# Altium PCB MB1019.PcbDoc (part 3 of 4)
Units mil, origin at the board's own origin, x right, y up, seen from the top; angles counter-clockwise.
Board outline 4655 x 6805 mil, 4 copper layers (TopLayer, VCC, GND, BottomLayer), stack 26.137 mil thick; 557 components, 425 nets, 1918 pads, 817 vias.
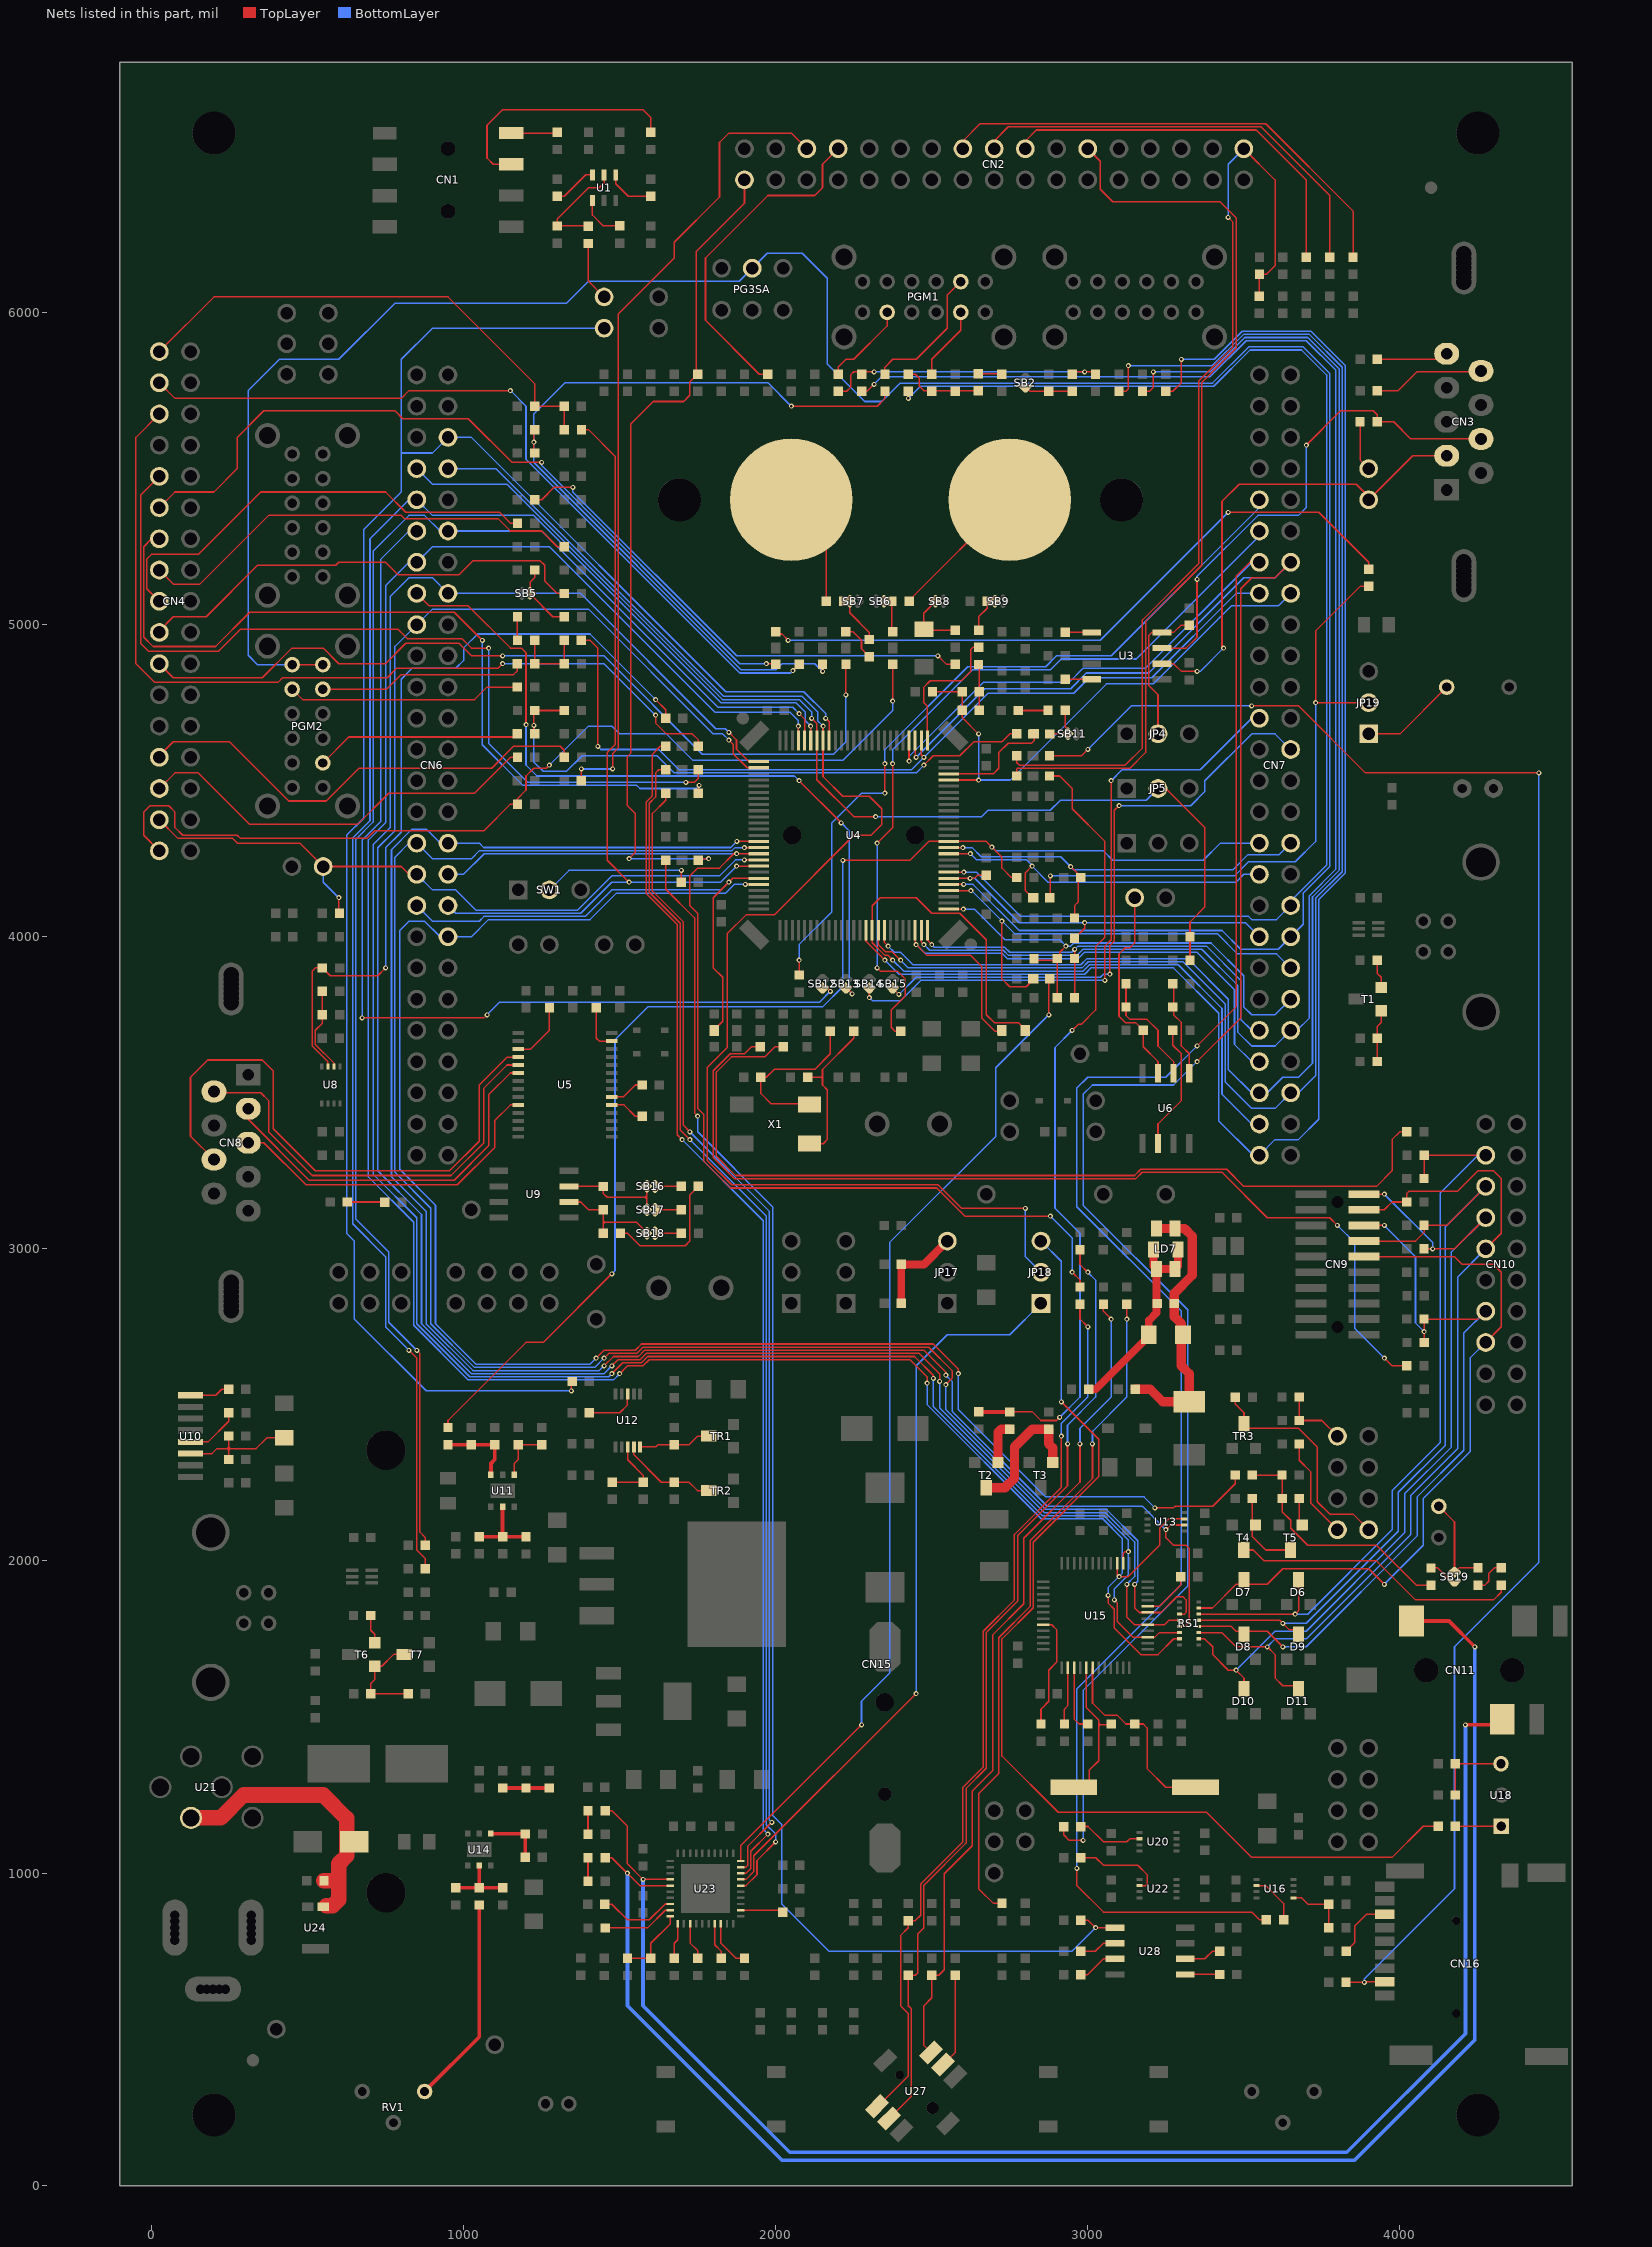
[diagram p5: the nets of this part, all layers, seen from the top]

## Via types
v1: diameter 16, hole 8, TopLayer to BottomLayer, tented both sides, 770 vias
v2: diameter 16, hole 8, TopLayer to BottomLayer, 26 vias
v3: diameter 25, hole 16, TopLayer to BottomLayer, tented both sides, 17 vias
v4: diameter 50, hole 28, TopLayer to BottomLayer, tented both sides, 4 vias

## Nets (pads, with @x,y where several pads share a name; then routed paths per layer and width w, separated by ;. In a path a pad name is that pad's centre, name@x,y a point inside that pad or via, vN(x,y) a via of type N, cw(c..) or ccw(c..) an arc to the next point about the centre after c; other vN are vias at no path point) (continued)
NetR31_1: CN2.11 R31.1 | length 2909.8
  TopLayer w5: R31.1@2772.5,4515 2772.5,4537.5 2775,4540 3135,4540 3185,4590 3185,5010 3365,5190 3365,5775.86 3475,5885.86 3475,6303.43 3423.43,6355 3080,6355 3040,6395 3040,6485 CN2.11@3000,6525
NetR33_1: C2.2 CN2.1 R33.1 R72.1 | length 3065.7
  TopLayer w5: R33.1@2772.5,4580 2772.5,4557.5 2780,4550 3120,4550 3175,4605 3175,5015 3355,5195 3355,5780 3465,5890 3465,6290 v1(3450,6305) ; CN2.1@3500,6525 3600,6425 3600,6150 3572.5,6122.5 C2.2@3550,6122.5 R72.1@3550,6052.5
  BottomLayer w5: v1(3450,6305) 3450,6475 CN2.1@3500,6525
NetR35_2: C134.1 R35.2 R128.1 R138.2 | length 1940.7
  TopLayer w5: R128.1@1225,4652.5 R138.2@1225,4722.5 ; R138.2@1227.5,4722.5 1227.5,4725 C134.1@1322.5,4725 ; v1(2475,4550) 2505,4580 2590,4580 2635,4625 2725,4625 2750,4650 R35.2@2773,4650
  BottomLayer w5: v1(1225,4677.5) 1225,4560 1255,4530 1330,4530 1380,4580 1620,4580 1675,4525 2450,4525 v1(2475,4550)
NetR36_2: R36.2 R137.1 SB11.2 | length 127.6
  TopLayer w5: R36.2@2877.5,4650 2925,4650 SB11.2@2932,4643 ; R137.1@2927.5,4725 2927.5,4672.5 SB11.2@2940,4660
NetR37_2: C21.1 R37.2 R131.1 | length 148.5
  TopLayer w5: R37.2@2650,4872.5 2652.5,4870 R131.1@2652.5,4725
NetR38_2: R38.2 R103.1 SB9.2 | length 103.9
  TopLayer w5: R38.2@2650,4982.5 2650,5025 2677.5,5052.5 R103.1@2677.5,5075
NetR39_1: R39.1 R96.1 | length 1607.9
  TopLayer w5: R96.1@1227.5,5400 1250,5400 1290,5440 v1(1350,5440) ; v1(2520,4900) 2547.5,4872.5 R39.1@2575,4872.5
  BottomLayer w5: v1(1350,5440) 1350,5425 1875,4900 v1(2520,4900)
NetR40_1: C52.2 R40.1 SB8.2 | length 246.1
  TopLayer w5: C52.2@2475,4985 2475,5036 SB8.2@2507,5068 ; 2475,5038 SB8.2@2512,5075 ; C52.2@2477.5,4982.5 R40.1@2575,4982.5
NetR41_1: C27.2 CN4.33 R41.1 | length 3076.8
  TopLayer w5: CN4.33@20,4280 CN4.33@25,4280 ; CN4.33@25,4275 -25,4325 -25,4400 -5,4420 55,4420 75,4400 75,4350 100,4325 275,4325 285,4315 690,4315 715,4340 1065,4340 1150,4425 C27.2@1172.5,4425 1172.5,4442.5 1200,4470 1200,4515 1225,4540 1265,4540 v1(1275,4550) ; v1(2375,4755) R41.1@2375,4872.5
  BottomLayer w5: v1(1275,4550) 1400,4675 1475,4675 1500,4650 1650,4650 1735,4565 2215,4565 2375,4725 v1(2375,4755)
NetR42_1: R42.1 R104.1 SB6.2 | length 119.5
  TopLayer w5: SB6.2@2348,5075 2372.5,5075 R42.1@2372.5,4980
NetR43_1: CN4.21 R43.1 | length 2716.7
  TopLayer w5: CN4.21@25,4875 70,4830 355,4830 450,4925 550,4925 600,4875 750,4875 815,4940 985,4940 1025,4900 v1(1125,4900) ; v1(2225,4775) R43.1@2225,4872.5
  BottomLayer w5: v1(1125,4900) 1450,4900 1765,4585 2185,4585 2225,4625 v1(2225,4775)
NetR44_1: R44.1 R122.2 | length 124.2
  TopLayer w5: R44.1@2225,4977.5 2247.5,4977.5 2275,4950 2275,4922.5 R122.2@2300,4897.5
NetR45_1: C133.1 R45.1 R90.2 R94.1 | length 2699.4
  TopLayer w5: C133.1@1225,5552.5 R90.2@1225,5622.5 ; R90.2@1227.5,5622.5 R90.2@1227.5,5625 ; v1(2050,5700) 2325,5700 2350,5725 R94.1@2350,5747.5 ; v1(2150,4850) R45.1@2150,4872.5
  BottomLayer w5: v1(2050,5700) 1975,5775 1325,5775 1225,5675 1225,5520 1890,4855 2000,4855 2020,4875 2125,4875 v1(2150,4850)
  other v1: 1225,5585
NetR47_1: CN4.3 R47.1 | length 2569.4
  TopLayer w5: CN4.3@25,5775 75,5725 800,5725 825,5750 v1(1150,5750) ; v1(2055,4852.5) 2075,4872.5 R47.1@2077.5,4872.5
  BottomLayer w5: v1(1150,5750) 1200,5700 1200,5530 1885,4845 2047.5,4845 v1(2055,4852.5)
NetR49_1: CN4.11 R49.1 | length 2510.9
  TopLayer w5: CN4.11@25,5375 75,5425 200,5425 275,5500 275,5600 360,5685 780,5685 805,5660 1015,5660 1155,5520 v1(1250,5520) ; v1(1970,4875) R49.1@1997.5,4875
  BottomLayer w5: CN4.11@25,5375 CN4.11@35,5375 ; v1(1250,5520) 1250,5510 1885,4875 v1(1970,4875)
NetR51_1: CN4.5 R51.1 | length 2819.4
  TopLayer w5: CN4.5@25,5675 -50,5600 -50,4875 10,4815 405,4815 420,4830 755,4830 785,4860 1110,4860 v1(1125,4875) ; v1(1615,4710) 1615,4685 1650,4650 1732.5,4650 1752.5,4630 R51.1@1752.5,4610
  BottomLayer w5: v1(1125,4875) 1450,4875 v1(1615,4710)
NetR53_1: CN4.9 R53.1 | length 2801
  TopLayer w5: CN4.9@25,5475 -35,5415 -35,4940 -10,4915 215,4915 285,4985 790,4985 820,4955 995,4955 1025,4925 v1(1080,4925) ; v1(1712.5,4495) 1740,4495 1752.5,4507.5 R53.1@1752.5,4535
  BottomLayer w5: v1(1080,4925) 1080,4620 1205,4495 v1(1712.5,4495)
NetR55_1: CN4.13 R55.1 | length 2648.8
  TopLayer w5: CN4.13@25,5275 0,5275 -25,5250 -25,4960 5,4930 205,4930 315,5040 970,5040 v1(1060,4950) ; R55.1@1752.5,4460 1752.5,4482.5 v1(1755,4485)
  BottomLayer w5: v1(1060,4950) 1060,4615 1190,4485 1555,4485 1565,4475 1745,4475 v1(1755,4485)
NetR57_1: C13.2 CN2.34 R57.1 | length 2693.6
  TopLayer w5: v1(1530,4250) 1550,4270 1550,4395 1525,4420 1525,4577.57 1536,4588.57 1536,5643.57 1607.43,5715 1705,5715 1725,5735 1725,5777.5 1745,5797.5 1745,6195 1900,6350 CN2.34@1900,6425 ; R57.1@1752.5,4250 v1(1785,4250)
  BottomLayer w5: v1(1530,4250) v1(1785,4250)
NetR59_2: CN1.1 R59.2 | length 150
  TopLayer w5: CN1.1@1152.5,6575 R59.2@1302.5,6575
NetR62_2: CN1.3 R62.2 | length 794.4
  TopLayer w5: CN1.3@1152.5,6475 1095,6475 1075,6495 1075,6600 1125,6650 1575,6650 1600,6625 R62.2@1600,6577.5
NetR63_2: R63.2 U1.6 | length 141.1
  TopLayer w5: R63.2@1300,6372.5 1322.5,6372.5 1391.34,6441.34 U1.6@1412.6,6441.34
NetR64_2: R64.2 U1.4 | length 157.9
  TopLayer w5: U1.4@1487.4,6441.34 1487.4,6412.6 1527.5,6372.5 R64.2@1600,6372.5
NetR66_1: R65.1 R66.1 U1.5 | length 345.9
  TopLayer w5: R66.1@1399,6276.5 1398,6277.5 1300,6277.5 1300,6300 1400,6400 1435,6400 1450,6415 U1.5@1450,6441.34
NetR66_2: JP1.2 R66.2 | length 192.6
  TopLayer w5: R66.2@1399,6221.5 1399,6101 JP1.2@1450,6050
NetR68_1: CN2.15 R68.1 | length 1253.3
  TopLayer w5: CN2.15@2800,6525 2800,6550 2835,6585 3540,6585 3700,6425 R68.1@3700,6177.5
NetR69_1: CN2.17 R69.1 | length 1407.3
  TopLayer w5: CN2.17@2700,6525 2700,6550 2745,6595 3555,6595 3775,6375 R69.1@3775,6177.5
NetR70_1: CN2.19 R70.1 | length 1561.3
  TopLayer w5: CN2.19@2600,6525 2600,6550 2655,6605 3570,6605 3850,6325 R70.1@3850,6177.5
NetR73_2: CN3.5 R73.2 | length 222.5
  TopLayer w5: R73.2@3927.5,5850 CN3.5@4150,5850
NetR79_1: C9.2 CN4.1 R78.1 R79.1 | length 1632.4
  TopLayer w5: CN4.1@25,5875 200,6050 950,6050 1227.5,5772.5 1227.5,5700 C9.2@1322.5,5700 R79.1@1322.5,5625
NetR81_1: CN2.27 R81.1 | length 1085.4
  TopLayer w5: R81.1@1975,5802.5 1947.5,5802.5 1775,5975 1775,6175 1975,6375 2125,6375 2150,6400 2150,6475 CN2.27@2200,6525
NetR83_2: C132.1 R75.2 R83.2 R95.1 | length 263.4
  TopLayer w5: R75.2@2425,5802.5 2447.5,5802.5 2460,5790 2460,5765 2475.5,5749.5 2649,5749.5 R83.2@2647,5747.5
NetR86_2: CN3.9 R86.2 | length 354.4
  TopLayer w5: R86.2@3927.5,5750 3995,5750 4055,5810 CN3.9@4257,5810
NetR87_2: JP3.1 R87.2 | length 161.4
  TopLayer w5: R87.2@3872.5,5650 3872.5,5527.5 JP3.1@3900,5500
NetR93_2: PGM1.2 R93.2 | length 277.9
  TopLayer w5: R93.2@2200,5802.5 2200,5825 2225,5850 2250,5850 2356.89,5956.89 PGM1.2@2356.89,6000.79
NetR94_2: PGM1.8 R94.2 | length 441.3
  TopLayer w5: R94.2@2350,5802.5 2350,5825 2375,5850 2450,5850 2550,5950 2550,6056.1 PGM1.8@2593.11,6099.21
NetR95_2: PGM1.5 R95.2 | length 239.4
  TopLayer w5: R95.2@2497.5,5802.5 2500,5802.5 2500,5850 2593.11,5943.11 PGM1.5@2593.11,6000.79
NetR97_1: CN4.17 R97.1 | length 1469.5
  TopLayer w5: CN4.17@25,5075 -15,5115 -15,5210 0,5225 150,5225 350,5425 750,5425 815,5360 1115,5360 1150,5325 R97.1@1172.5,5325
NetR98_2: C131.1 R74.2 R93.1 R98.2 | length 924.3
  TopLayer w5: R93.1@2200,5747.5 2227.5,5747.5 2240,5760 2240,5800 2250,5810 v1(2315,5810) ; R98.2@2945,5810 C131.1@3030,5810
  BottomLayer w5: v1(2315,5810) v1(2990,5810)
NetR99_1: CN4.15 R99.1 | length 1448.7
  TopLayer w5: CN4.15@25,5175 70,5130 155,5130 375,5350 800,5350 810,5340 1110,5340 1150,5300 1250,5300 1300,5250 R99.1@1322.5,5250
NetR101_1: CN4.19 R101.1 | length 1496.6
  TopLayer w5: CN4.19@25,4980 70,5025 175,5025 340,5190 590,5190 600,5200 750,5200 790,5160 985,5160 1030,5205 1245,5205 1260,5190 1260,5140 1300,5100 R101.1@1322.5,5100
NetR102_2: R102.2 TS1.1 | length 371.6
  TopLayer w5: TS1.1@2050,5400 2162.5,5287.5 R102.2@2162.5,5075
NetR104_2: R104.2 TS2.1 | length 458.6
  TopLayer w5: R104.2@2427.5,5075 2427.5,5077.5 TS2.1@2750,5400
NetR105_1: R105.1 U3.1 | length 85
  TopLayer w5: R105.1@2927.5,4975 U3.1@3012.5,4975
NetR106_1: JP4.2 R106.1 U3.8 | length 470.9
  TopLayer w5: JP4.2@3225,4650 3225,4775 3195,4805 3195,4965 3205,4975 3275,4975 3297.5,4997.5 R106.1@3325,4997.5
NetR107_2: C135.1 R107.2 R109.1 R110.2 | length 245
  TopLayer w5: R107.2@1227.5,4950 1227.5,4875 1322.5,4875 R110.2@1322.5,4950
NetR109_2: PGM2.5 R109.2 | length 670.4
  TopLayer w5: PGM2.5@549.21,4793.11 753.11,4793.11 800,4840 1160,4840 1172.5,4852.5 R109.2@1172.5,4875
NetR111_1: R111.1 R313.2 | length 2163.9
  TopLayer w5: R313.2@2725,902.5 2697.5,902.5 2650,950 2650,1254.29 2715,1319.29 2715,1754.14 2815,1854.14 2815,2064.29 3015,2264.29 v1(3015,2375) ; v1(3125,2775) R111.1@3125,2822.5
  BottomLayer w5: v1(3015,2375) 3015,2415 3125,2525 v1(3125,2775)
NetR113_1: R98.1 R113.1 SB2.2 | length 156
  TopLayer w5: SB2.2@2800,5762 2814.5,5747.5 R98.1@2950,5747.5
NetR116_1: R83.1 R116.1 | length 76.8
  TopLayer w5: R83.1@2649,5804.5 2723,5804.5 R116.1@2725,5802.5
NetR120_2: PGM2.8 R120.2 | length 752
  TopLayer w5: PGM2.8@450.79,4793.11 483.9,4760 1035,4760 1075,4800 R120.2@1172.5,4800
NetR122_1: R102.1 R122.1 SB7.2 | length 148.6
  TopLayer w5: SB7.2@2237,5075 2237,5038 2300,4975 R122.1@2300,4952.5
NetR124_2: R124.2 U3.4 | length 85
  TopLayer w5: R124.2@2927.5,4825 U3.4@3012.5,4825
NetR128_2: PGM2.2 R128.2 | length 655.2
  TopLayer w5: PGM2.2@549.21,4556.89 632.32,4640 R128.2@1170,4640
NetR129_1: R129.1 R186.1 U8.3 | length 2591.6
  TopLayer w5: U8.3@565.16,3584.06 565.16,3599.84 515,3650 515,3890 525,3900 547.5,3900 572.5,3875 725,3875 v1(750,3900) ; v1(1615,4760) 1647.62,4727.38 R129.1@1647.62,4699.84 ; R129.1@1647.5,4700 R129.1@1647.62,4700.12
  BottomLayer w5: v1(750,3900) 750,4285 800,4335 800,4825 835,4860 975,4860 1000,4885 1000,4925 1045,4970 1405,4970 v1(1615,4760)
NetR132_1: R107.1 R132.1 | length 75
  TopLayer w5: R107.1@1172.5,4950 R132.1@1172.5,5025
NetR134_1: R108.1 R134.1 SB5.2 | length 213.7
  TopLayer w5: SB5.2@1213,5100 1213,5135.5 1227.5,5150 R134.1@1227.5,5175 ; SB5.2@1218,5093 1286,5025 R108.1@1322.5,5025
NetR137_2: C24.2 R137.2 | length 95
  TopLayer w5: C24.2@2777.5,4725 R137.2@2872.5,4725
NetR139_1: R139.1 R140.1 U16.5 | length 196.9
  TopLayer w5: U16.5@3659.06,920.47 3685,920.47 3705.47,900 R140.1@3772.5,900 R139.1@3772.5,825
NetR145_1: CN4.29 R145.1 | length 1322.1
  TopLayer w5: CN4.29@27.5,4477.5 75,4525 150,4525 315,4360 660,4360 760,4460 1035,4460 1150,4575 R145.1@1172.5,4575
NetR147_1: CN4.27 R147.1 | length 1495
  TopLayer w5: CN4.27@25,4580 70,4625 250,4625 440,4435 560,4435 665,4540 1090,4540 1160,4610 1310,4610 1322.5,4597.5 R147.1@1322.5,4575
NetR148_1: CN2.29 R148.1 | length 2600
  TopLayer w5: R148.1@1377.5,4500 v1(1377.5,4537.5) ; v1(1477.5,4537.5) 1477.5,4587.5 1496,4606 1496,5996 1675,6175 1675,6225 1820,6370 1820,6545 1850,6575 2050,6575 CN2.29@2100,6525
  BottomLayer w5: v1(1377.5,4537.5) v1(1477.5,4537.5)
NetR159_1: JP19.2 R20.2 R159.1 | length 2042.1
  TopLayer w5: R20.2@2880,4127.5 v1(2880,4195) ; R159.1@3900,5122.5 3872.5,5122.5 3730,4980 v1(3730,4750) JP19.2@3905,4750
  BottomLayer w5: v1(2880,4195) 3470,4195 3515,4240 3665,4240 3730,4305 v1(3730,4750)
NetR159_2: R50.1 R159.2 | length 2166.9
  TopLayer w5: R50.1@2000,4970 2020,4970 v1(2040,4950) ; v1(3450,5360) 3740,5360 3900,5200 R159.2@3900,5177.5
  BottomLayer w5: v1(2040,4950) 3040,4950 v1(3450,5360)
NetR166_2: R166.2 SW1.2 | length 485.9
  TopLayer w5: R166.2@1697.5,4175 v1(1697.5,4212.5)
  BottomLayer w5: SW1.2@1275,4150 1337.5,4212.5 v1(1697.5,4212.5)
NetR177_1: R177.1 R189.1 U8.2 | length 275.1
  TopLayer w5: R177.1@547.5,3825 547.5,3722.5 525,3700 525,3655 584.84,3595.16 U8.2@584.84,3584.06
NetR185_1: R185.1 T1.1 | length 92.7
  TopLayer w5: R185.1@3927.5,3925 3927.5,3882.5 3940,3870 T1.1@3940,3837.5
NetR187_2: CN7.9 R187.2 | length 2426.4
  TopLayer w5: R187.2@2075,3877.5 v1(2075,3925) ; v1(2350,4460) v1(2350,4555)
  BottomLayer w5: v1(2075,3925) 2075,3975 2180,4080 2180,4365 2275,4460 v1(2350,4460) ; v1(2350,4555) 2350,4600 2615,4865 2865,4865 2900,4900 3075,4900 3550,5375 CN7.9@3550,5400
NetR196_1: C45.1 R196.1 X1.1 | length 554.5
  TopLayer w5: X1.1@2115,3465 1985,3465 1952.5,3497.5 C45.1@1952.5,3550 1970,3550 1995,3575 2125,3575 2175,3625 R196.1@2175,3697.5
NetR197_1: C50.1 R197.1 X1.4 | length 518.9
  TopLayer w5: C50.1@2102.5,3550 2150,3550 ; X1.4@2108.27,3337.01 2152.01,3337.01 2165,3350 2165,3510 2150,3525 2150,3575 2250,3675 R197.1@2250,3697.5 ; 2150,3545 2145,3550 2150,3555
NetR201_2: R201.2 U6.2 | length 405
  TopLayer w5: U6.2@3225,3337.5 3225,3400 3300,3475 3300,3625 3272.5,3652.5 R201.2@3272.5,3700
NetR202_2: R202.2 U5.20 | length 113.8
  TopLayer w5: U5.20@1474.61,3486.61 1511.61,3486.61 1550,3525 R202.2@1572.5,3525
NetR206_1: CN7.11 R206.1 | length 2507.8
  TopLayer w5: v1(2325,3900) 2335,3890 2390,3890 2415,3865 2415,3810 2370,3765 2370,3710 2382.5,3697.5 R206.1@2400,3697.5 ; v1(2325,4300) 2375,4350 v1(2375,4555)
  BottomLayer w5: v1(2325,3900) v1(2325,4300) ; v1(2375,4555) 2375,4600 2630,4855 2880,4855 2915,4890 3155,4890 3550,5285 CN7.11@3550,5300
NetR213_2: R213.2 R214.1 T1.2 | length 167.7
  TopLayer w5: R214.1@3927.5,3600 3927.5,3712.5 3940,3725 T1.2@3940,3762.5
NetR215_2: R215.2 U5.19 | length 112.8
  TopLayer w5: U5.19@1474.61,3461.02 1513.98,3461.02 1550,3425 R215.2@1572.5,3425
NetR216_2: R6.1 R216.2 | length 2917.7
  TopLayer w5: R6.1@2024,3647.5 1997.5,3647.5 1965,3615 1858.28,3615 1810,3566.72 1810,3296.57 1871.57,3235 3150,3235 3170,3255 3445,3255 3500,3200 3925,3200 3975,3250 3975,3350 4000,3375 R216.2@4022.5,3375
NetR219_1: C54.2 R219.1 SB18.2 U9.6 | length 355.6
  TopLayer w5: U9.6@1337.5,3150 1375,3150 1400,3125 1447.5,3125 C54.2@1447.5,3050 ; 1447.5,3080 1452.5,3085 1447.5,3090 ; 1447.5,3085 1554,3085 SB18.2@1582,3057
NetR220_1: R220.1 SB16.2 SB17.2 U9.7 | length 359.3
  TopLayer w5: U9.7@1337.5,3200 1447.5,3200 1447.5,3177.5 1460,3165 1587,3165 ; SB17.2@1587,3132 SB16.2@1587,3200 ; 1587,3160 1582,3165 1587,3170
NetR221_1: C54.1 R221.1 | length 431.7
  TopLayer w5: C54.1@1502.5,3050 1525,3050 1565,3010 1710,3010 1725,3025 1725,3172.5 R221.1@1752.5,3200
NetR221_2: R221.2 SB16.1 | length 82.8
  TopLayer w5: SB16.1@1618,3192 1626,3200 R221.2@1697.5,3200
NetR222_1: JP17.3 R222.1 R231.1 | length 303.6
  TopLayer w25: R231.1@2402.5,2825 2402.5,2950 2475,2950 JP17.3@2550,3025
NetR225_1: LD5.1 R225.1 | length 120
  TopLayer w5: LD5.1@627.5,3150 R225.1@747.5,3150
NetR226_1: R226.1 SB17.1 | length 77.5
  TopLayer w5: SB17.1@1620,3125 R226.1@1697.5,3125
NetR230_1: R230.1 SB18.1 | length 72.5
  TopLayer w5: SB18.1@1625,3050 R230.1@1697.5,3050
NetR238_2: C55.2 C56.1 LD7.1 LD7.2 LD7.3 LD7.4 R238.2 | length 681
  TopLayer w5: C56.1@3195,2720 C56.1@3195,2725
  TopLayer w25: R238.2@3002.5,2550 3025,2550 C56.1@3195,2720 ; C56.1@3195,2725 3195,2770 3220,2795 LD7.1@3220,2934.57 ; LD7.3@3210.63,2998.03 3210.63,2944.88 LD7.1@3220.47,2935.04 LD7.2@3279.53,2935.04 3289.37,2944.88 LD7.4@3289.37,2998.03
NetR242_2: R4.1 R242.2 | length 3136.8
  TopLayer w5: R4.1@1950,3647.5 1922.5,3647.5 1900,3625 1854.14,3625 1800,3570.86 1800,3292.43 1867.43,3225 3154.14,3225 3174.14,3245 3430,3245 3575,3100 3775,3100 v1(3800,3075) ; v1(3950,2650) 3975,2625 R242.2@4022.5,2625
  BottomLayer w5: v1(3800,3075) 3855,3020 3855,2745 v1(3950,2650)
NetR243_2: R243.2 U10.1 | length 130.4
  TopLayer w5: U10.1@125,2530.91 205.91,2530.91 225,2550 R243.2@247.5,2550
NetR246_1: C71.1 R246.1 U11.1 | length 176.5
  TopLayer w5: U11.1@1162.4,2276.18 1162.4,2312.4 1175,2325 C71.1@1175,2372.5 R246.1@1250,2372.5
NetR247_1: R247.1 U12.3 | length 168
  TopLayer w5: R247.1@1402.5,2475 1500,2475 1525,2500 1525,2533.69 U12.3@1526,2534.69
NetR248_2: C55.1 C56.2 LD7.5 LD7.6 R248.2 R261.2 | length 887.4
  TopLayer w30: R248.2@3152.5,2550 3200,2550 3240,2510 R261.2@3325,2510 3325,2600 3300,2625 3300,2760 3277.5,2782.5 3277.5,2857.5 3335,2915 3335,3040 3310.04,3064.96 LD7.5@3220.47,3064.96
NetR249_1: CN15.8 R249.1 TR3.3 | length 733.7
  TopLayer w5: R249.1@3472.5,2525 3472.5,2502.5 3500.5,2474.5 TR3.3@3500.5,2440 ; TR3.3@3500,2425 3675,2425 3735,2365 3735,2190 3775,2150 3850,2150 CN15.8@3900,2100
NetR250_2: CN15.1 R240.1 R250.2 | length 218.2
  TopLayer w5: R240.1@3677.5,2525 3677.5,2450 3750,2450 CN15.1@3800,2400
NetR252_2: C61.1 C62.1 R252.2 U10.6 | length 424.5
  TopLayer w5: U10.6@125,2343.9 193.9,2343.9 210,2360 335,2360 370,2395 C62.1@425,2395 ; C61.1@247.5,2325 R252.2@247.5,2400 ; 242.5,2360 247.5,2355 252.5,2360 247.5,2365 242.5,2360
NetR254_2: C58.1 R245.2 R254.2 U11.3 | length 251.5
  TopLayer w12: R245.2@950,2372.5 C58.1@1100,2372.5 1100,2325 1087.6,2312.6 U11.3@1087.6,2276.18
NetR257_1: R32.1 R256.2 R257.1 | length 2555.3
  TopLayer w5: R257.1@2750,2477.5 2822.5,2477.5 2850,2450 2900,2450 v1(2910,2460) ; R32.1@2877.5,4515 2910,4515 2950,4475 2950,4410 3055,4305 3055,3998.43 3025,3968.43 3025,3765 2980,3720 2970,3720 v1(2950,3700)
  TopLayer w12: R256.2@2650,2477.5 R257.1@2750,2477.5
  BottomLayer w5: v1(2910,2460) 2975,2525 2975,3050 2895,3130 2895,3645 v1(2950,3700)
NetR257_2: R257.2 T2.2 | length 139.1
  TopLayer w30: T2.2@2712.5,2315 2712.5,2412.5 2722.5,2422.5 R257.2@2750,2422.5
NetR258_2: R258.2 T2.3 T3.2 | length 449.4
  TopLayer w30: T2.3@2674.5,2235 2735,2235 2765,2265 2765,2365 2822.5,2422.5 2875,2422.5 2875,2375 2887.5,2362.5 T3.2@2887.5,2315
NetR262_1: R262.1 R264.2 R275.1 R280.2 | length 802
  TopLayer w5: R262.1@3527.5,2275 3622.5,2275 3622.5,2157.5 3650,2130 3650,2105 3705,2050 3925,2050 4052.5,1922.5 R280.2@4100,1922.5
NetR263_2: CN15.7 R263.2 | length 325.7
  TopLayer w5: R263.2@3677.5,2375 3677.5,2322.5 3715,2285 3715,2185 CN15.7@3800,2100
NetR267_1: C70.1 R267.1 R278.2 U11.5 | length 246.3
  TopLayer w12: R278.2@1050,2077.5 R267.1@1200,2077.5 ; C70.1@1125,2077.5 U11.5@1125,2173.82
NetR275_2: R275.2 T5.2 | length 87.5
  TopLayer w5: T5.2@3677.5,2112.5 R275.2@3677.5,2200
NetR277_1: C73.1 R277.1 U14.1 | length 185.6
  TopLayer w12: U14.1@1087.4,1126.18 1196.32,1126.18 1197.5,1125 C73.1@1197.5,1050
NetR280_1: R280.1 SB19.1 | length 85.8
  TopLayer w5: R280.1@4100,1977.5 4121.5,1977.5 SB19.1@4167,1932
NetR281_2: LD9.2 R281.2 SB19.2 | length 305.2
  TopLayer w5: LD9.2@4125,2175 4175,2125 SB19.2@4175,1963 ; SB19.2@4181,1969 4189.5,1977.5 R281.2@4250,1977.5
NetR282_1: R282.1 T4.3 | length 924.6
  TopLayer w5: T4.3@3499.5,2035 3530,2035 3565,2000 3925,2000 4050,1875 4300,1875 4325,1900 R282.1@4325,1922.5
NetR282_2: R281.1 R282.2 | length 112.4
  TopLayer w5: R281.1@4250,1922.5 4272.5,1922.5 4285,1935 4285,1960 4302.5,1977.5 R282.2@4325,1977.5
NetR283_2: R283.2 R284.1 T6.2 T7.3 | length 323.4
  TopLayer w5: T7.3@810,1700.5 775.5,1700.5 737.5,1662.5 T6.2@715,1662.5 715,1620 702.5,1607.5 702.5,1575 R284.1@822.5,1575
NetR285_1: C77.1 R285.1 R286.2 U14.5 | length 222.3
  TopLayer w5: R285.1@1050,951.5 R285.1@1050,952.5
  TopLayer w12: C77.1@975,952.5 R286.2@1125,952.5 ; R285.1@1050,952.5 U14.5@1050,1023.82
NetR290_2: L3.1 R290.2 R293.2 | length 150
  TopLayer w12: L3.1@1125,1272.5 R293.2@1275,1272.5
NetR291_2: R291.2 U15.2 | length 184.9
  TopLayer w5: R291.2@2925,1477.5 2925,1525 2936.42,1536.42 U15.2@2936.42,1657.68
NetR295_2: R295.2 U15.3 | length 214.5
  TopLayer w5: U15.3@2956.1,1657.68 2956.1,1493.9 2972.5,1477.5 R295.2@3000,1477.5
NetR300_1: JP18.3 R300.1 | length 3428.6
  TopLayer w5: v1(2915,2510) 3035,2390 3035,2270.15 2825,2060.15 2825,1850 2725,1750 2725,1375 2905,1195 3380,1195 3525,1050 3975,1050 4075,1150 R300.1@4122.5,1150
  BottomLayer w5: JP18.3@2850,3025 2915,2960 v1(2915,2510)
NetR300_2: R300.2 U18.1 | length 140
  TopLayer w5: R300.2@4185,1150 U18.1@4325,1150
NetR301_2: C98.1 R301.2 | length 75
  TopLayer w5: R301.2@1398.5,1124 C98.1@1398.5,1199
NetR302_2: C102.1 R302.2 | length 75
  TopLayer w5: R302.2@1398.5,974 C102.1@1398.5,1049
NetR303_1: R303.1 U22.2 | length 291.2
  TopLayer w5: R303.1@2977.38,1049.16 3025.84,1049.16 3050,1025 3160,1025 3190,995 3190,965 3184.84,959.84 U22.2@3165.94,959.84
NetR304_1: R304.1 U23.32 | length 128.4
  TopLayer w5: U23.32@1887.99,881.1 R304.1@2016.4,881.1
NetR307_1: C124.2 R307.1 U27.1 | length 2889.3
  TopLayer w5: U27.1@2330,255 2425,350 2425,550 2400,575 2400,800 2425,825 C124.2@2425,847.5 2447.5,847.5 2465,865 2465,965 2600,1100 2600,1275 2665,1340 2665,1775 2765,1875 2765,2085 2915,2235 v1(2915,2400) ; R307.1@2975,2822.5 2975,2775 v1(3000,2750)
  BottomLayer w5: v1(2915,2400) 2915,2440 3000,2525 v1(3000,2750)
NetR308_1: C126.2 R308.1 U27.2 | length 3099.9
  TopLayer w5: U27.2@2363.7,213.7 2435,285 2435,565 2425,575 C126.2@2425,672.5 2447.5,672.5 2455,680 2455,805 2475,825 2475,960.86 2610,1095.86 2610,1270.86 2675,1335.86 2675,1770.71 2775,1870.71 2775,2080.86 2935,2240.86 v1(2935,2375) ; R308.1@2975,2997.5 2975,2950 v1(3000,2925)
  BottomLayer w5: v1(2935,2375) 2935,2435 3025,2525 3025,2900 v1(3000,2925)
NetR309_1: C125.2 R309.1 U27.6 | length 2678.5
  TopLayer w5: U27.6@2497.33,425.27 2475,447.6 2475,575 2500,600 C125.2@2500,672.5 2522.5,672.5 2540,690 2540,997.57 2630,1087.57 2630,1262.57 2695,1327.57 2695,1762.43 2795,1862.43 2795,2072.57 2975,2252.57 v1(2975,2375) ; R309.1@3050,2822.5 3050,2800 v1(3075,2775)
  BottomLayer w5: v1(2975,2375) 2975,2425 3075,2525 v1(3075,2775)
NetR310_1: R310.1 U16.2 | length 162.6
  TopLayer w5: U16.2@3540.94,959.84 3570.16,959.84 3627.38,902.62 R310.1@3627.38,850.16
NetR311_2: CN16.7 R311.2 | length 203.9
  TopLayer w5: R311.2@3827.62,749.84 3855,777.21 3855,830 3892.91,867.91 CN16.7@3951.65,867.91
NetR314_2: R58.1 R314.2 U28.1 | length 4722.4
  TopLayer w5: R58.1@1647.5,4250 1647.5,4152.5 1740,4060 1740,3435 v1(1750,3425) ; R314.2@2977.5,849 3001,849 v1(3025,825) U28.1@3087.5,825
  BottomLayer w5: v1(1750,3425) 1750,3375 1990,3135 1990,1185 2020,1155 2020,900 2170,750 2950,750 v1(3025,825)
NetR315_1: R315.1 U28.6 | length 120.4
  TopLayer w5: U28.6@3312.5,725 3375,725 3400,750 R315.1@3422.5,750
NetR318_1: R318.1 U28.2 | length 120.8
  TopLayer w5: R318.1@2977.5,749 3024,749 3050,775 U28.2@3087.5,775
NetR319_1: R319.1 U28.5 | length 110
  TopLayer w5: U28.5@3312.5,675 R319.1@3422.5,675
NetR320_1: CN16.2 R34.1 R320.1 | length 5953.9
  TopLayer w5: R34.1@2877.5,4580 2980,4580 v1(3000,4600) ; v1(3525,4740) 3675,4740 3890,4525 v2(4445,4525) ; R320.1@3827.54,650 v2(3886.38,650) 3887.76,651.38 CN16.2@3951.65,651.38
  BottomLayer w5: v1(3000,4600) 3140,4740 v1(3525,4740) ; v2(3886.38,650) 3886.38,661.38 4175,950 4175,1725 4445,1995 v2(4445,4525)
NetR326_2: R326.2 U27.5 | length 302.2
  TopLayer w5: U27.5@2536.3,386.3 2575,425 R326.2@2575,672.5
NetR328_2: R328.2 U28.3 | length 131.1
  TopLayer w5: R328.2@2977.5,674 2999,674 3050,725 U28.3@3087.5,725
NetRS1_4: CN9.10 CN10.15 D7.3 RS1.4 | length 2282.9
  TopLayer w5: RS1.4@3356,1849.21 3399.21,1849.21 3475,1925 3575,1925 3625,1975 3900,1975 v1(3950,1925) ; CN9.10@3885,2975 4175,2975 4200,2950 4300,2950 4325,2925 4325,2750 CN10.15@4275,2700
  BottomLayer w5: v1(3950,1925) 4075,2050 4075,2200 4225,2350 4225,2650 CN10.15@4275,2700
NetRS1_6: CN10.3 D6.3 R218.1 R223.2 RS1.6 | length 2468.7
  TopLayer w5: RS1.6@3356,1829.53 v1(3664.53,1829.53) 3675.5,1840.5 D6.3@3675.5,1940 3675,1939.5 D6.3@3675,1950 ; R218.1@4077.5,3225 4077.5,3300 CN10.3@4275,3300
  BottomLayer w5: v1(3664.53,1829.53) 3704.53,1829.53 3975,2100 3975,2225 4130,2380 4130,3180 4250,3300 CN10.3@4275,3300
NetRS1_8: CN9.8 CN10.5 D9.3 R229.1 RS1.8 | length 2525.2
  TopLayer w5: RS1.8@3356,1809.84 3615.16,1809.84 3645,1780 D9.3@3680,1780 ; CN9.8@3885,3025 4050,3025 4077.5,3052.5 4077.5,3075 4150,3075 CN10.5@4275,3200
  BottomLayer w5: v1(3625,1800) 3700,1800 3995,2095 3995,2220 4145,2370 4145,3070 CN10.5@4275,3200
NetRS1_10: CN9.6 CN10.13 D8.3 R235.1 R241.2 RS1.10 | length 2424.8
  TopLayer w5: RS1.10@3356,1790.16 3459.84,1790.16 3475,1775 3575,1775 v1(3625,1725) ; CN9.6@3885,3075 v1(3950,3075) ; R241.2@4077.5,2700 4077.5,2775 4250,2775 CN10.13@4275,2800
  BottomLayer w5: v1(3625,1725) 3700,1725 4055,2080 4055,2205 4205,2355 4205,2730 CN10.13@4275,2800 ; v1(3950,3075) 4050,2975 4050,2762.5 v1(4077.5,2735)
NetRS1_12: CN9.4 CN10.9 D11.3 R224.2 RS1.12 | length 2821.2
  TopLayer w5: RS1.12@3356,1770.47 3429.53,1770.47 3475,1725 v1(3575,1725) 3600,1700 3600,1625 3625,1600 3674.5,1600 D11.3@3675,1600.5 ; CN9.4@3885,3125 3950,3125 3975,3150 4022.5,3150 4022.5,3177.5 4030,3185 4185,3185 4250,3250 4300,3250 4325,3225 4325,3050 CN10.9@4275,3000
  BottomLayer w5: v1(3575,1725) 3600,1750 3700,1750 4035,2085 4035,2210 4185,2360 4185,2910 CN10.9@4275,3000
NetRS1_14: CN9.2 CN10.7 D10.3 R233.1 RS1.14 | length 2629
  TopLayer w5: RS1.14@3356,1750.79 3374.21,1750.79 3400,1725 3400,1700 3450,1650 v1(3475,1650) 3500.5,1624.5 D10.3@3500.5,1590 ; CN9.2@3885,3175 v1(3950,3175) ; R233.1@4077.5,3000 4175,3000 CN10.7@4275,3100
  BottomLayer w5: v1(3475,1650) 3600,1775 3700,1775 4015,2090 4015,2215 4165,2365 4165,2990 CN10.7@4275,3100 ; v1(3950,3175) 4105,3020 v1(4105,3000)
NetRV1_1: R285.2 RV1.1 | length 670
  TopLayer w12: RV1.1@875,300 1050,475 R285.2@1050,897.5
NetSB12_2: CN6.11 SB12.2 | length 3214.3
  TopLayer w5: v1(675,3740) 1065,3740 v1(1075,3750) ; SB12.2@2148,3837 2163,3837 v1(2175,3825)
  BottomLayer w5: v1(675,3740) 675,4310 735,4370 735,5210 825,5300 CN6.11@850,5300 ; v1(1075,3750) 1115.32,3790.32 2140.32,3790.32 v1(2175,3825)
NetSB13_2: CN6.15 SB13.2 | length 2466.1
  TopLayer w5: CN6.15@850,5100 890,5060 1015,5060 1150,4925 1185,4925 1200,4910 v1(1200,4680) ; v1(2075,4500) v1(2210,4365) ; SB13.2@2225,3837 v1(2245,3817)
  BottomLayer w5: v1(1200,4680) 1200,4550 1235,4515 2060,4515 v1(2075,4500) ; v1(2210,4365) 2235,4340 2235,3827 v1(2245,3817)
NetSB14_2: CN7.23 SB14.2 | length 2049.2
  TopLayer w5: v1(2300,3805) SB14.2@2300,3837 ; v1(3055,3860) 3055,3970.15 3075,3990.15 v1(3075,4500) ; CN7.23@3525,4700 CN7.23@3550,4700
  BottomLayer w5: v1(2300,3805) 2310,3795 2400,3795 2465,3860 v1(3055,3860) ; v1(3075,4500) 3110,4535 3360,4535 3525,4700 CN7.23@3550,4700
NetSB15_2: CN7.26 SB15.2 | length 1969.7
  TopLayer w5: SB15.2@2375,3835 v1(2395,3815) ; v1(3071,3880) 3071,3972 3085,3986 3085,4405 v1(3100,4420)
  BottomLayer w5: v1(2395,3815) 2450,3870 3040,3870 3050,3880 v1(3071,3880) ; v1(3100,4420) 3330,4420 3375,4465 3375,4500 3525,4650 3600,4650 CN7.26@3650,4600
NetT5_3: R271.1 T4.2 T5.3 | length 262.1
  TopLayer w5: R271.1@3527.5,2200 3527.5,2077.5 3570,2035 T5.3@3649.5,2035
NetT6_1: R272.1 T6.1 | length 92.7
  TopLayer w5: R272.1@702.5,1825 702.5,1777.5 715,1765 T6.1@715,1737.5
NetU1_1: R71.2 U1.1 | length 148.1
  TopLayer w5: U1.1@1412.6,6358.66 1412.6,6312.4 1447.5,6277.5 R71.2@1500,6277.5
NetU2_1: JP19.1 U2.1 | length 312.1
  TopLayer w5: JP19.1@3900,4650 4000,4650 U2.1@4150,4800
NetU3_6: CN3.2 JP3.2 U3.6 | length 1536
  TopLayer w5: U3.6@3237.5,4875 3275,4875 3300,4850 v1(3350,4850) ; v1(3435,4925) 3430,4930 3430,5395 3485,5450 3860.56,5450 JP3.2@3905.28,5405.28 ; JP3.2@3900,5400 4041,5541 CN3.2@4150,5541
  BottomLayer w5: v1(3350,4850) 3360,4850 v1(3435,4925)
NetU3_7: CN3.7 R87.1 U3.7 | length 1619.1
  TopLayer w5: U3.7@3237.5,4925 3315,4925 3350,4960 v1(3350,5145) ; v1(3700,5575) 3810,5685 3915,5685 3927.5,5672.5 3927.5,5650 3980,5650 4035,5595 CN3.7@4260,5595
  BottomLayer w5: v1(3350,5145) 3350,5155 3545,5350 3675,5350 3700,5375 v1(3700,5575)
NetU5_3: C42.1 U5.3 | length 196.9
  TopLayer w5: U5.3@1175.39,3640.16 1215.16,3640.16 1275,3700 C42.1@1275,3772.5
NetU5_4: CN8.8 U5.4 | length 1880.1
  TopLayer w5: CN8.8@200,3286 125,3361 125,3550 180,3605 355,3605 390,3570 390,3385 525,3250 955,3250 1050,3345 1050,3525 1139.57,3614.57 U5.4@1175.39,3614.57
NetU5_5: CN8.6 U5.5 | length 1394.5
  TopLayer w5: CN8.6@200,3504 204,3500 350,3500 375,3475 375,3375 515,3235 960,3235 1065,3340 1065,3515 1138.98,3588.98 U5.5@1175.39,3588.98
NetU5_6: CN8.2 U5.6 | length 1218.1
  TopLayer w5: CN8.2@310,3449 310,3415 505,3220 970,3220 1080,3330 1080,3493.39 1150,3563.39 U5.6@1175.39,3563.39
NetU5_10: CN8.3 U5.10 | length 1077.8
  TopLayer w5: CN8.3@310,3340 360,3340 495,3205 980,3205 1100,3325 1100,3411.02 1150,3461.02 U5.10@1175.39,3461.02
NetU5_27: C43.1 U5.27 | length 150.9
  TopLayer w5: C43.1@1425,3772.5 1425,3675 1434.25,3665.75 U5.27@1474.61,3665.75
NetU6_5: R184.1 R200.1 U6.5 | length 309.2
  TopLayer w5: R184.1@3272.5,3850 3275,3847.5 3275,3750 3300,3725 3300,3650 3325,3625 U6.5@3325,3562.5
NetU6_6: R181.1 R199.1 U6.6 | length 382.9
  TopLayer w5: R181.1@3122.5,3850 3122.5,3747.5 3135,3735 3190,3735 3225,3700 3225,3650 3275,3600 U6.6@3275,3562.5
NetU6_7: JP8.1 R212.2 U6.7 | length 662.8
  TopLayer w5: JP8.1@3150,4125 3150,3980 3135,3965 3120,3965 3100,3945 3100,3745 3120,3725 3152.5,3725 3177.5,3700 3177.5,3647.5 3225,3600 U6.7@3225,3562.5
NetU10_5: R244.1 U10.5 | length 177.4
  TopLayer w5: U10.5@125,2381.3 181.3,2381.3 247.5,2447.5 R244.1@247.5,2475
NetU12_8: R268.2 R269.2 U12.8 | length 233.5
  TopLayer w5: R268.2@1476,2252.5 1576,2252.5 1576,2274 1526,2324 U12.8@1526,2365.31
NetU12_9: R270.2 TR2.3 U12.9 | length 312.1
  TopLayer w5: U12.9@1545.69,2365.31 1545.69,2340 1633.19,2252.5 1722.5,2252.5 1749.5,2225.5 TR2.3@1785,2225.5
NetU12_10: R255.2 TR1.3 U12.10 | length 244
  TopLayer w5: U12.10@1565.37,2365.31 1615.31,2365.31 1622.5,2372.5 1722.5,2372.5 1750,2400 TR1.3@1795,2400
NetU15_20: R279.1 U15.20 | length 160.8
  TopLayer w5: U15.20@3192.32,1854.53 3229.53,1854.53 3297.5,1922.5 R279.1@3297.5,1950
NetU15_44: R294.2 U15.44 | length 371.9
  TopLayer w5: R294.2@2850,1477.5 2850,1525 2875,1550 2875,1650 2900,1675 2900,1780 2884.53,1795.47 U15.44@2857.68,1795.47
NetU18_3: C90.1 R296.1 U18.3 | length 246.5
  TopLayer w5: R296.1@4177.5,1250 C90.1@4177.5,1350 U18.3@4324,1350
NetU20_2: R299.2 U20.2 | length 212.8
  TopLayer w5: R299.2@2977.5,1149 3001,1149 3050,1100 3125,1100 3134.84,1109.84 U20.2@3165.94,1109.84
NetU23_14: C98.2 CN11.4 U23.14 | length 4872.1
  TopLayer w5: C98.2@1453.5,1199 1476,1199 1525,1150 1525,1029.53 1575,979.53 U23.14@1662.01,979.53
  TopLayer w12: v1(4210,1475) CN11.4@4330,1475
  BottomLayer w12: v1(1575,980) 1575,575 2045,105 3830,105 4210,485 4210,1465 v1(4210,1475)
NetU23_15: C102.2 CN11.6 U23.15 | length 5247.2
  TopLayer w5: C102.2@1453.5,1049 1475,1049 v1@1524.5,999.5 ; v1(1525,1000) 1525,999 1564.16,959.84 U23.15@1662.01,959.84
  TopLayer w12: CN11.6@4037.17,1807.48 4157.52,1807.48 v1(4240,1725)
  BottomLayer w12: v1(1525,1000) 1525,575 2020,80 3855,80 4240,465 v1(4240,1725)
NetU23_18: C112.2 U23.18 | length 251.3
  TopLayer w5: C112.2@1452.5,900 1475,900 1525,850 1595,850 1645.79,900.79 U23.18@1662.01,900.79
NetU23_19: C111.2 U23.19 | length 232.2
  TopLayer w5: C111.2@1453.5,824 1589,824 1646.1,881.1 U23.19@1662.01,881.1
NetU23_20: C118.1 R323.2 U23.20 | length 235.6
  TopLayer w5: R323.2@1525,726.5 C118.1@1600,726.5 1600,775 1662.01,837.01 U23.20@1662.01,861.42
NetU23_21: C119.1 U23.21 | length 115.2
  TopLayer w5: C119.1@1675,726.5 1675,775 1686.42,786.42 U23.21@1686.42,837.01
NetU23_23: C120.1 U23.23 | length 120.5
  TopLayer w5: U23.23@1725.79,837.01 1725.79,775.79 1750,751.57 C120.1@1750,726.5
NetU23_27: C128.2 U23.27 | length 119
  TopLayer w5: U23.27@1804.53,837.01 1804.53,770.47 1825,750 C128.2@1825,726.5
NetU23_28: C127.2 U23.28 | length 159.5
  TopLayer w5: U23.28@1824.21,837.01 1824.21,775.79 1873.5,726.5 C127.2@1900,726.5 C127.2@1898.5,725
NetU23_36: R54.1 U23.36 | length 3834.2
  TopLayer w5: R54.1@1647.5,4535 1625,4535 1615,4525 1615,4447.57 1595,4427.57 1595,4142.43 1694.31,4043.12 1694.31,3380.69 v1(1725,3350) ; U23.36@1887.99,959.84 1905,959.84 1940,994.84 1940,1040 v1(2000,1100)
  BottomLayer w5: v1(1725,3350) 1970,3105 1970,1155 2000,1125 v1(2000,1100)
NetU23_37: JP18.1 U23.37 | length 2371.1
  TopLayer w5: U23.37@1887.99,979.53 1905,979.53 1930,1004.53 1930,1055 v1(2450,1575)
  BottomLayer w5: v1(2450,1575) 2450,2625 2550,2725 2750,2725 JP18.1@2850,2825
NetU23_38: R52.1 U23.38 | length 3854.5
  TopLayer w5: R52.1@1647.5,4610 1630,4610 1605,4585 1605,4451.72 1585,4431.72 1585,4138.28 1684.31,4038.97 1684.31,3365.69 v1(1700,3350) ; U23.38@1887.99,999.21 1905,999.21 1920,1014.21 1920,1070 v1(1975,1125)
  BottomLayer w5: v1(1700,3350) 1960,3090 1960,1140 v1(1975,1125)
NetU23_39: R56.1 U23.39 | length 3668.2
  TopLayer w5: R56.1@1647.5,4460 1647.5,4437.5 1605,4395 1605,4146.57 1704.31,4047.26 1704.31,3395.69 v1(1725,3375) ; U23.39@1887.99,1018.9 1905,1018.9 1910,1023.9 1910,1085 1987.39,1162.39 v1(1987.39,1162.61)
  BottomLayer w5: v1(1725,3375) 1980,3120 1980,1170 v1(1987.39,1162.61)
NetU23_40: R16.2 U23.40 | length 3232.7
  TopLayer w5: U23.40@1887.99,1038.58 1887.99,1087.99 v1(2275,1475) ; v1(2875,3750) R16.2@2875,3862.5
  BottomLayer w5: v1(2275,1475) 2275,1550 2365,1640 2365,3020 2705,3360 2705,3580 v1(2875,3750)
NetU24_3: C97.1 U21.1 U24.3 Z1.2 | length 926
  TopLayer w50: U21.1@126.57,1176.57 221.57,1176.57 295,1250 550,1250 625,1175 625,1055 600,1030 600,915 580,895 U24.3@560,895 ; C97.1@552.5,975 600,975
OSC_IN: C88.2 U15.5 X4.2 | length 473.1
  TopLayer w5: U15.5@2995.47,1657.68 2995.47,1529.53 3035,1490 3035,1360 3005,1330 X4.2@3005,1265 ; 3035,1470 3040,1475 3035,1480 ; 3035,1475 C88.2@3072.5,1475
OSC_OUT: C89.2 U15.6 X4.1 | length 630.6
  TopLayer w5: U15.6@3015.16,1657.68 3015.16,1544.84 3055,1505 3095,1505 3122.5,1477.5 3177.5,1477.5 3190,1465 3190,1335 3250,1275 X4.1@3345,1275
PA0: CN7.45 R9.1 R10.1 U4.23 | length 1908.2
  TopLayer w5: U4.23@2446.85,4020.87 2446.85,3978.15 2485,3940 2625,3940 2660,3905 2660,3740 2702.5,3697.5 R9.1@2725,3697.5
  BottomLayer w5: v1(2450,3975) 2478.27,3946.73 2724.98,3946.73 2741.72,3930 2969.14,3930 2989.14,3950 3350,3950 3470,3830 3470,3655 3525,3600 CN7.45@3550,3600
PA1: CN7.44 R74.1 U4.24 | length 5297.6
  TopLayer w5: R74.1@2275,5747.5 2292.5,5747.5 v1(2315,5770) ; U4.24@2466.53,4020.87 2466.53,3983.47 v1(2475,3975)
  BottomLayer w5: v1(2315,5770) 2339,5794 3391.43,5794 3507.43,5910 3700,5910 3795,5815 3795,4216.72 3710,4131.72 3710,3740 3670,3700 CN7.44@3650,3700 3600,3650 3525,3650 3480,3695 3480,3845 3365,3960 2985,3960 2965,3940 2745.86,3940 2729.13,3956.73 2493.27,3956.73 v1(2475,3975)
PA2: C37.1 CN7.43 R115.1 U4.25 | length 1459.5
  TopLayer w5: U4.25@2486.22,4020.87 2486.22,3988.78 v1(2500,3975) ; C37.1@2957.5,3805 v1(2957.5,3959.23)
  BottomLayer w5: v1(2500,3975) 2508.27,3966.73 2733.27,3966.73 2750,3950 2948.27,3950 2968.27,3970 3380,3970 3490,3860 3490,3735 3525,3700 CN7.43@3550,3700
PA3: C37.2 CN7.42 R114.2 R115.2 U4.26 | length 1567.1
  TopLayer w5: U4.26@2554.13,4088.78 v1(2601.22,4088.78) ; R114.2@2827.5,3925 2902.5,3925 C37.2@2902.5,3805 ; R115.2@2910,3930 2910,3950 v1(2930,3970)
  BottomLayer w5: v1(2601.22,4088.78) 2636.22,4088.78 2735,3990 2910,3990 v1(2930,3970) 2945,3970 2955,3980 3395,3980 3500,3875 3500,3775 3525,3750 3600,3750 CN7.42@3650,3800
PA4: CN7.40 R15.1 R16.1 U4.29 | length 1506.7
  TopLayer w5: U4.29@2554.13,4147.83 v1(2625.32,4147.83) ; v1(2725,4050) 2725,3865 2750,3840 2802.5,3840 R15.1@2827.5,3865
  BottomLayer w5: v1(2625.32,4147.83) 2627.17,4147.83 2765,4010 3415,4010 3480,3945 3605,3945 CN7.40@3650,3900
PA5: CN7.38 PG3SA.5 PGM2.6 PGM2.9 U4.30 | length 8267.7
  TopLayer w5: PGM2.9@450.79,4871.85 PGM2.6@549.21,4871.85 ; U4.30@2554.13,4167.52 v1(2602.48,4167.52)
  BottomLayer w5: PGM2.9@450.79,4871.85 340,4871.85 310,4901.85 310,5750 410,5850 600,5850 780,6030 1330,6030 1400,6100 1883.07,6100 1973.07,6190 2085,6190 2165,6110 2165,5835 2285,5715 2340,5715 2399,5774 3399.71,5774 3515.71,5890 3690,5890 3775,5805 3775,4225 3690,4140 3690,4040 3610,3960 3490,3960 3430,4020 2780,4020 2632.48,4167.52 v1(2602.48,4167.52)
PA6: C33.1 CN7.37 R118.1 U4.31 | length 1193.3
  TopLayer w5: U4.31@2554.13,4187.2 2637.2,4187.2 2647.5,4197.5 C33.1@2675,4197.5 ; R118.1@2957.5,3995 2990,4027.5 v1(2990,4045)
  BottomLayer w5: v1(2622.8,4187.2) 2637.8,4187.2 2780,4045 3505,4045 CN7.37@3550,4000
PA7: CN7.36 R75.1 U4.32 | length 4384.9
  TopLayer w5: v1(2425,5725) R75.1@2425,5747.5 ; U4.32@2554.13,4206.89 v1(2603.11,4206.89)
  BottomLayer w5: v1(2425,5725) 2464,5764 3403.85,5764 3519.85,5880 3685,5880 3765,5800 3765,4229.14 3650,4114.14 CN7.36@3650,4100 3605,4055 3525,4055 3515,4065 2785,4065 2643.11,4206.89 v1(2603.11,4206.89)
PA8: CN6.6 JP1.1 R237.1 U4.67 | length 6497.9
  TopLayer w5: v1(1345,2545) R237.1@1345,2565.55 ; v1(2160,4700) 2171.26,4688.74 U4.67@2171.26,4629.13
  BottomLayer w5: 800,5550 900,5550 CN6.6@950,5600 1025,5600 1840,4785 2090,4785 2160,4715 v1(2160,4700) ; v1(1345,2545) 880,2545 650,2775 650,3025 625,3050 625,4325 680,4380 680,5305 800,5425 800,5850 900,5950 JP1.1@1450,5950
PA9: CN6.8 JP18.2 U4.68 | length 4705.1
  TopLayer w5: v1(2151.57,4675) 2151.57,4513.43 2215,4450 2300,4450 2340,4410 2340,4360 2305,4325 2250,4325 1995,4070 1905,4070 1845,4010 1845,3645 1780,3580 1780,3284.14 1859.14,3205 2520,3205 2595,3130 v1(2800,3130)
  BottomLayer w5: CN6.8@950,5500 1103.28,5500 1833.28,4770 2085,4770 2135,4720 2135,4691.57 v1(2151.57,4675) ; v1(2800,3130) 2800,2975 JP18.2@2850,2925
PA10: CN6.7 JP5.2 R182.2 R183.2 U4.69 | length 3638.2
  TopLayer w5: v1(2115,4700) 2131.89,4683.11 2131.89,4503.11 2250,4385 v1(2320,4385) ; JP5.2@3225,4475 3250,4475 3375,4350 3375,4095 3327.5,4047.5 R182.2@3327.5,3925
  BottomLayer w5: CN6.7@850,5500 900,5450 1139.14,5450 1829.14,4760 2075.86,4760 2115,4720.86 v1(2115,4700) ; v1(2320,4385) 2660,4385 2680,4405 2880,4405 2912.5,4437.5 3187.5,4437.5 JP5.2@3225,4475
PA11: CN6.9 R266.1 U4.70 | length 5245.5
  TopLayer w5: v1(825,2675) 850,2650 850,2035 877.5,2007.5 R266.1@877.5,1975 ; U4.70@2112.2,4629.13 v1(2112.2,4675)
  BottomLayer w5: v1(825,2675) 750,2750 750,2975 645,3080 645,4316.72 700,4371.72 700,5275 825,5400 CN6.9@850,5400 900,5350 1225,5350 1825,4750 2065,4750 2095,4720 2095,4692.2 v1(2112.2,4675)
PA12: CN6.12 R260.1 U4.71 | length 5068.8
  TopLayer w5: v1(850,2675) 860,2665 860,2092.5 877.5,2075 R260.1@877.5,2050 ; v1(2075,4715) 2092.52,4697.48 U4.71@2092.52,4629.13
  BottomLayer w5: v1(850,2675) 760,2765 760,2990 655,3095 655,4312.57 710,4367.57 710,5235 825,5350 875,5350 925,5300 1250,5300 1815,4735 2055,4735 v1(2075,4715)
PA13: CN6.13 RS1.13 U4.72 U13.7 U15.27 | length 7722.7
  TopLayer w5: v1(1500,2600) 1525,2625 1575,2625 1595,2645 2430,2645 2485,2590 v1(2485,2570) ; U4.72@2072.83,4629.13 v1(2072.83,4674.68) ; v1(3065,1890) 3065,1865 3085,1845 3085,1785 3170,1700 3225,1700 3275.79,1750.79 RS1.13@3294,1750.79 ; U15.27@3093.9,1992.32 3093.9,1956.1 v1(3100,1950) 3130,1950 3230,2050 3230,2105 3259.84,2134.84 U13.7@3309.06,2134.84
  BottomLayer w5: v1(1500,2600) 1480,2580 1015,2580 840,2755 840,3085 695,3230 695,4310 750,4365 750,5125 825,5200 CN6.13@850,5200 900,5250 1275,5250 1805,4720 2045,4720 2072.83,4692.17 v1(2072.83,4674.68) ; v1(2485,2570) 2485,2500.86 2850.86,2135 3047.57,2135 3110,2072.57 3110,1960 3065,1915 v1(3065,1890)
PA14: CN6.16 RS1.11 U4.76 U15.15 U15.26 | length 7117.6
  TopLayer w5: v1(1475,2600) 1510,2635 1570,2635 1590,2655 2445,2655 2505,2595 v1(2505,2585) ; v1(1850,4655) 1874.38,4630.62 1874.38,4600.62 1913.78,4561.22 U4.76@1945.87,4561.22 ; v1(3085,1875) 3095,1865 3095,1805 3143.9,1756.1 3215,1756.1 3229.37,1770.47 RS1.11@3294,1770.47 ; U15.26@3113.58,1992.32 3113.58,2023.58 3120,2030 v1(3130,2030)
  BottomLayer w5: v1(1475,2600) 1465,2590 1020,2590 850,2760 850,3100 710,3240 710,4295 765,4350 765,5090 825,5150 900,5150 CN6.16@950,5100 1375,5100 1808.25,4666.75 1838.25,4666.75 v1(1850,4655) ; v1(2505,2585) 2505,2495 2855,2145 3051.72,2145 3130,2066.72 3130,1955 3085,1910 v1(3085,1875)
PA15: CN6.17 RS1.7 U4.77 U15.17 | length 6823
  TopLayer w5: v1(1475,2625) 1495,2645 1565,2645 1585,2665 2460,2665 2525,2600 v1(2525,2575) ; v1(1850,4630) 1864.38,4615.62 1864.38,4585.62 1908.47,4541.53 U4.77@1945.87,4541.53 ; v1(3125,1925) 3125,1820.47 3150,1795.47 3245.47,1795.47 3259.84,1809.84 RS1.7@3294,1809.84
  BottomLayer w5: v1(1475,2625) 1450,2600 1025,2600 865,2760 865,3110 725,3250 725,4285 780,4340 780,4930 900,5050 1400,5050 1800,4650 1830,4650 v1(1850,4630) ; v1(2525,2575) 2525,2490.86 2860.86,2155 3055.86,2155 3150,2060.86 3150,1950 v1(3125,1925)
PB0: CN7.33 R19.1 R20.1 U4.35 | length 1164.2
  TopLayer w5: U4.35@2554.13,4265.94 v1(2624.06,4265.94) ; v1(2821.44,4226.44) 2800,4205 2800,4147.5 R19.1@2822.5,4125
  BottomLayer w5: v1(2624.06,4265.94) 2643.42,4246.58 2803.42,4246.58 v1@2822.5,4227.5 ; v1(2821.44,4226.44) 2872.88,4175 3475,4175 3500,4200 CN7.33@3550,4200
PB1: C29.1 CN7.32 R135.1 U4.36 | length 1340.9
  TopLayer w5: U4.36@2554.13,4285.63 v1(2599.37,4285.63) ; v1(2945,4225) 2970,4200 2970,4112.5 2957.5,4100 R135.1@2957.5,4060
  BottomLayer w5: v1(2599.37,4285.63) 2629.37,4285.63 2658.42,4256.58 2913.42,4256.58 2955,4215 3465,4215 3512.12,4262.12 3612.12,4262.12 CN7.32@3650,4300
PB2: CN7.31 R21.1 R245.1 U4.37 | length 4257.7
  TopLayer w5: R245.1@950,2420 950,2450 1200,2700 1255,2700 v1(1475,2920) ; v1(2215,4245) 2430,4245 2490.32,4305.32 2674.68,4305.32 2725,4255 2725,4220 2755,4190 R21.1@2772.5,4190
  BottomLayer w5: v1(1475,2920) 1485,2930 1485,3670 1590,3775 2150,3775 2215,3840 v1(2215,4245) ; v1(2692.6,4287.4) 2705,4275 3050,4275 3080,4245 3370,4245 3425,4300 CN7.31@3550,4300
PB3: CN6.32 RS1.9 U4.89 U13.6 | length 5987.4
  TopLayer w5: v1(1450,2625) 1480,2655 1560,2655 1580,2675 2475,2675 2545,2605 v1(2545,2595) ; v1(1875.31,4305.32) U4.89@1945.87,4305.32 ; RS1.9@3294,1790.16 3310.16,1790.16 3325,1805 3325,2040 3315,2050 3275,2050 3250,2075 v1(3250,2100) 3265.16,2115.16 U13.6@3309.06,2115.16
  BottomLayer w5: CN6.32@925,4300 880,4345 835,4345 769,4279 769,3231 879.85,3120.15 879.85,2760.15 1030,2610 1435,2610 v1(1450,2625) ; CN6.32@950,4300 1050,4300 1064.06,4285.94 1855.94,4285.94 v1(1875.31,4305.32) ; v1(2545,2595) 2565,2575 2565,2480 2870,2175 3175,2175 v1(3250,2100)
PB4: CN6.31 RS1.5 U4.90 U15.19 | length 5949.4
  TopLayer w5: v1(1450,2650) 1465,2665 1555,2665 1575,2685 2490,2685 2565,2610 2565,2585 v1(2545,2565) ; v1(1900,4285.63) U4.90@1945.87,4285.63 ; v1(3150,1925) 3150,1850 3165.16,1834.84 3234.84,1834.84 3285,1885 3305,1885 3315,1875 3315,1835 3309.53,1829.53 RS1.5@3294,1829.53
  BottomLayer w5: v1(1450,2650) 1420,2620 1035,2620 895,2760 895,3130 780,3245 780,4255 825,4300 CN6.31@850,4300 900,4250 1025,4250 1050.94,4275.94 1860.09,4275.94 1869.77,4285.63 v1(1900,4285.63) ; v1(2545,2565) 2545,2485 2865,2165 3060,2165 3160,2065 3160,1935 v1(3150,1925)
PB5: CN6.34 R307.2 U4.91 | length 3586.1
  TopLayer w5: U4.91@1945.87,4265.94 1865.94,4265.94 1820,4220 1750,4220 1724.31,4194.31 1724.31,4100 1750,4074.31 1750,3450 1770,3430 1770,3280 1855,3195 2515.86,3195 2605.86,3105 v1(2880,3105) ; v1(2950,2925) 2975,2900 R307.2@2975,2877.5
  BottomLayer w5: CN6.34@950,4200 1000,4200 1065.94,4265.94 v1(1875,4265.94) ; v1(2880,3105) 2950,3035 v1(2950,2925)
PB6: C35.2 CN4.31 CN6.33 JP7.1 U4.92 | length 2276
  TopLayer w5: CN4.31@25,4375 85,4315 260,4315 275,4300 475,4300 JP7.1@550,4225 800,4225 825,4200 CN6.33@850,4200 ; C35.2@600,4077.5 v1(600,4125) ; v1(1900,4246.26) U4.92@1945.87,4246.26
  BottomLayer w5: JP7.1@550,4225 550,4175 v1(600,4125) ; CN6.33@850,4200 900,4150 975,4150 1040,4085 1365,4085 1475,4195 1820,4195 1871.26,4246.26 v1(1900,4246.26)
PB7: CN6.36 R79.2 U4.93 | length 2621.9
  TopLayer w5: R79.2@1377.5,5625 1400,5625 1486,5539 1486,4616 1460,4590 1460,4245 v1(1530,4175) ; v1(1875,4226.58) U4.93@1945.87,4226.58
  BottomLayer w5: CN6.36@945,4100 CN6.36@950,4100 975,4075 1375,4075 1475,4175 1823.43,4175 v1(1875,4226.58)
PB8: CN6.35 R17.1 R18.1 U4.95 | length 1690.3
  TopLayer w5: R17.1@1803,3702.5 1830,3729.5 1830,3870 1800,3900 1800,4125 1862.2,4187.2 U4.95@1945.87,4187.2
  BottomLayer w5: CN6.35@850,4100 900,4050 1050,4050 1065,4065 1390,4065 1475,4150 1825,4150 v1(1850.03,4175.03)
PB9: CN6.38 R262.2 U4.96 | length 5532.5
  TopLayer w5: v1(1425,2650) 1450,2675 1550,2675 1570,2695 2505,2695 2585,2615 v1(2585,2600) ; v1(1902.52,4167.52) U4.96@1945.87,4167.52 ; v1(3215,2170) 3275,2170 3280,2175 3400,2175 3472.5,2247.5 R262.2@3472.5,2275
  BottomLayer w5: CN6.38@925,4000 875,4050 825,4050 795,4020 795,3255 910,3140 910,2760 1040,2630 1405,2630 v1(1425,2650) ; CN6.38@950,4000 1025,4000 1080,4055 1405,4055 1490,4140 1840,4140 1867.52,4167.52 v1(1902.52,4167.52) ; v1(2585,2600) 2585,2485 2865,2205 3180,2205 v1(3215,2170)
PB10: C21.2 CN7.16 R130.2 R131.2 U4.47 | length 1743.1
  TopLayer w5: R130.2@2502.5,4785 C21.2@2597.5,4785 2597.5,4702.5 v1(2650,4650) ; U4.47@2554.13,4502.17 v1(2650,4502.17)
  BottomLayer w5: v1(2650,4650) v1(2650,4502.17) 2752.17,4502.17 3060,4810 3210,4810 3460,5060 3610,5060 CN7.16@3650,5100
PB11: R35.1 R36.1 U4.48 | length 369.1
  TopLayer w5: U4.48@2554.13,4521.85 2696.85,4521.85 2715,4540 2715,4590 2745,4620 2820,4620 2828,4628 R35.1@2828,4650
PB12: R37.1 R38.1 U4.51 | length 444.3
  TopLayer w5: U4.51@2486.22,4629.13 2486.22,4738.78 2475,4750 2475,4800 2495,4820 2595,4820 2625,4850 2625,4920 2632.5,4927.5 R37.1@2650,4927.5
PB13: CN7.15 R110.1 U4.52 | length 2820.6
  TopLayer w5: R110.1@1377.5,4950 1405,4950 1430,4925 v1(1430,4610) ; U4.52@2466.53,4629.13 2466.53,4583.47 v1(2475,4575)
  BottomLayer w5: v1(1430,4610) 1440,4600 1625,4600 1690,4535 2435,4535 2680,4780 2955,4780 3005,4830 3205,4830 3475,5100 CN7.15@3550,5100
PB14: CN7.14 R299.1 U4.53 | length 6454.6
  TopLayer w5: U4.53@2446.85,4629.13 2446.85,4578.15 v1(2450,4575) ; R299.1@2922.62,1148.84 2922.62,1122.38 2940,1105 v2(2985,1105) ; v1(3350.19,3600.19) 3490,3740 3490,5115 3525,5150 3600,5150 CN7.14@3650,5200
  BottomLayer w5: v1(2450,4575) 2670,4795 2945,4795 2995,4845 3195,4845 3500,5150 3600,5150 CN7.14@3650,5200 ; v2(2985,1105) 2985,1585 3320,1920 3320,2805 2985,3140 2985,3495 3015,3525 3275,3525 v1(3350.19,3600.19)
PB15: CN7.13 R310.2 U4.54 | length 7038.2
  TopLayer w5: v1(2427.16,4562.84) U4.54@2427.16,4629.13 ; v2(2965,1015) 2965,960 3050,875 3525,875 3549.84,850.16 R310.2@3572.38,850.16 ; v1(3350,3650) 3475,3775 3475,5155 3520,5200 CN7.13@3550,5200
  BottomLayer w5: v1(2427.16,4562.84) 2427.16,4577.16 2665,4815 2940,4815 2985,4860 3185,4860 3525,5200 CN7.13@3550,5200 ; v2(2965,1015) 2965,1590 3300,1925 3300,2800 2965,3135 2965,3515 3000,3550 3250,3550 v1(3350,3650)
PC0: CN7.51 R85.2 U4.15 | length 5230.6
  TopLayer w5: U4.15@2289.37,4020.87 2289.37,3985.63 v1(2350,3925) ; R85.2@3250,5747.5 3272.5,5747.5 3300,5775 v1(3300,5850)
  BottomLayer w5: v1(2350,3925) 2395,3880 2989.85,3880 3009.85,3900 3275,3900 3420,3755 3420,3410 3530,3300 CN7.51@3550,3300 3600,3350 3675,3350 3740,3415 3740,4119.29 3825,4204.29 3825,5830 3715,5940 3495,5940 3405,5850 v1(3300,5850)
PC1: CN7.49 R13.2 R14.2 U4.16 | length 2594.6
  TopLayer w5: v1(2375,3925) 2358.78,3941.22 2348.78,3941.22 2309.05,3980.95 2309.05,4099.05 2335,4125 2450,4125 2500,4075 2590,4075 2675,3990 2675,3750 2700,3725 2777.5,3725 R13.2@2800,3702.5
  BottomLayer w5: v1(2375,3925) 2410,3890 2985.71,3890 3005.71,3910 3290,3910 3430,3770 3430,3495 3525,3400 CN7.49@3550,3400
PC2: CN7.48 R84.1 U4.17 | length 5068.2
  TopLayer w5: U4.17@2328.74,4035 2328.74,3975.4 2352.93,3951.22 2373.78,3951.22 v1(2400,3925) ; R84.1@3100,5747.5 3122.5,5747.5 3130,5755 v1(3130,5830)
  BottomLayer w5: v1(2400,3925) 2425,3900 2981.57,3900 3001.57,3920 3305,3920 3440,3785 3440,3535 3525,3450 3600,3450 CN7.48@3650,3500 3675,3500 3730,3555 3730,4123.43 3815,4208.43 3815,5825 3710,5930 3499.14,5930 3399.14,5830 v1(3130,5830)
PC3: CN7.47 R77.1 U4.18 | length 4830.4
  TopLayer w5: U4.18@2348.42,4020.87 2348.42,3981.58 v1(2360,3970) ; R77.1@3175,5747.5 3197.5,5747.5 3210,5760 v1(3210,5810)
  BottomLayer w5: v1(2360,3970) 2380,3950 2400,3950 2440,3910 2977.43,3910 2997.43,3930 3320,3930 3450,3800 3450,3575 3525,3500 3575,3500 3625,3550 3675,3550 3720,3595 3720,4127.57 3805,4212.57 3805,5820 3705,5920 3503.28,5920 3393.28,5810 v1(3210,5810)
